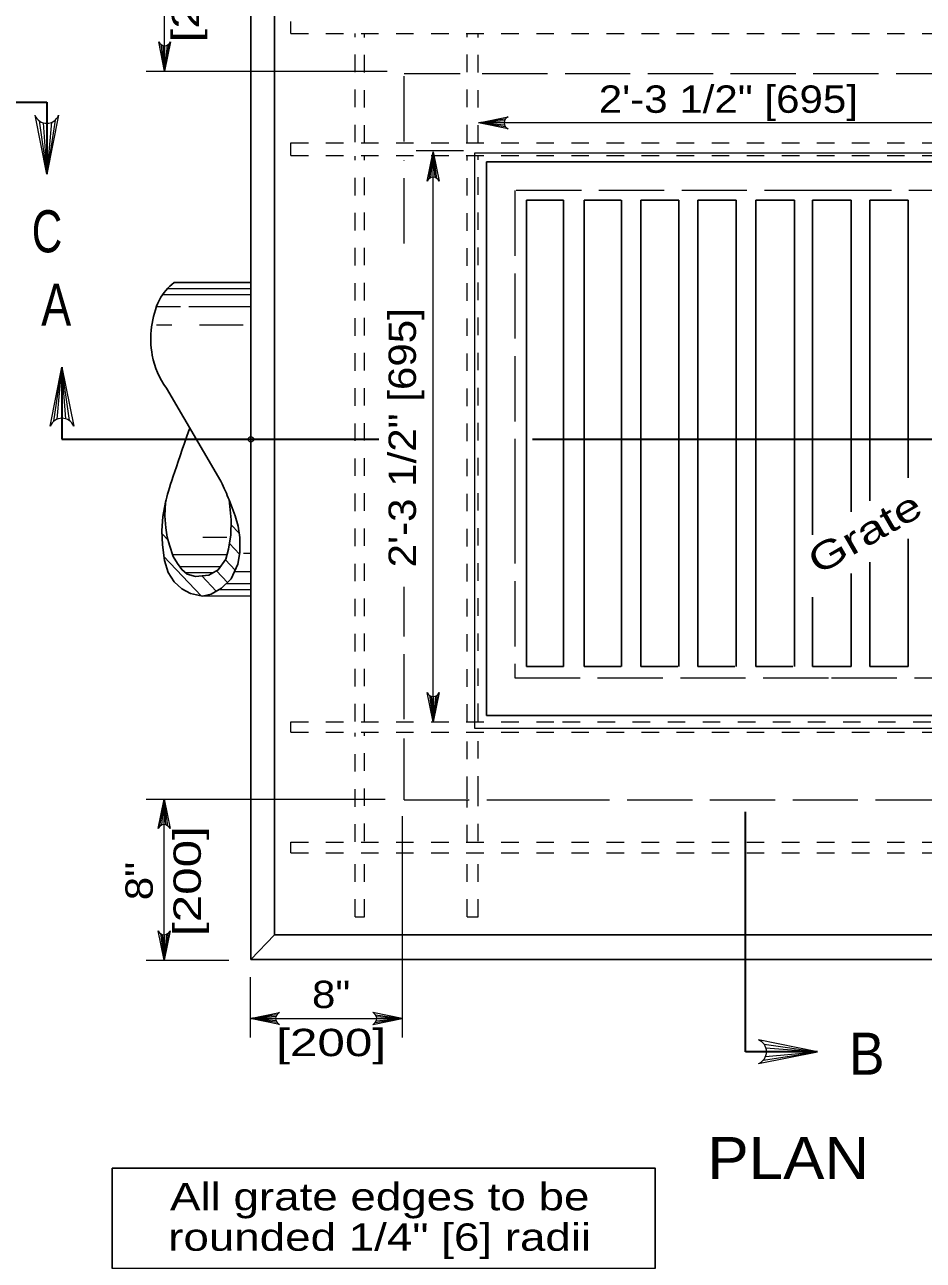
# Model space of a CAD drawing. Extents: x 1083.1 to 1117.1, y 697.4 to 719.4.
# Drawn here: x 1099.92 to 1105.05, y 708.27 to 715.32 of the extents above; entities that cross this region are included whole.
import ezdxf
from ezdxf.enums import TextEntityAlignment as Align

# ---------------------------------------------------------------- set-up
doc = ezdxf.new("R2010")
doc.units = 0
doc.header["$LTSCALE"] = 0.062
doc.header["$PDMODE"] = 32
doc.header["$PDSIZE"] = 0.031
doc.linetypes.add('DOTTED', pattern=[1.5, 0.3, -1.2])
doc.linetypes.add('LONG_DASHED', pattern=[7.5, 6, -1.5])
doc.layers.add('1', color=7, linetype='Continuous', lineweight=13)

msp = doc.modelspace()

# ---------------------------------------------------------------- linework, layer by layer
at = {"layer": '1'}
for p, q in [((1100.72158, 715.05042), (1100.72158, 715.96892)), ((1100.70025, 715.20267), (1100.72158, 715.05042)), ((1100.71083, 715.1975), (1100.72158, 715.05042)), ((1100.74517, 715.2045), (1100.72158, 715.05042)), ((1100.73525, 715.19867), (1100.72158, 715.05042)), ((1100.72158, 715.196), (1100.72158, 715.05042)), ((1100.61667, 715.05042), (1101.99075, 715.05042)), ((1100.00717, 714.76733), (1100.04975, 714.46275)), ((1100.09692, 714.77092), (1100.04975, 714.46275)), ((1102.66442, 714.77742), (1102.51208, 714.75608)), ((1102.65925, 714.76683), (1102.51208, 714.75608)), ((1100.02825, 714.757), (1100.04975, 714.46275)), ((1100.07717, 714.75925), (1100.04975, 714.46275)), ((1100.04975, 714.75392), (1100.04975, 714.46275)), ((1102.65767, 714.75608), (1102.51208, 714.75608)), ((1102.66033, 714.74242), (1102.51208, 714.75608)), ((1102.66617, 714.73258), (1102.51208, 714.75608)), ((1105.562, 714.75608), (1102.51208, 714.75608)), ((1102.426, 714.59675), (1102.15683, 714.59675)), ((1102.22967, 714.43742), (1102.25317, 714.5915)), ((1102.2395, 714.44325), (1102.25317, 714.5915)), ((1102.25317, 712.52158), (1102.25317, 714.5915)), ((1102.25317, 714.44592), (1102.25317, 714.5915)), ((1102.26392, 714.44433), (1102.25317, 714.5915)), ((1102.2745, 714.43917), (1102.25317, 714.5915)), ((1101.2135, 713.77592), (1100.709, 713.77592)), ((1101.2135, 713.81042), (1100.737, 713.81042)), ((1100.81175, 713.70667), (1100.67467, 713.70667)), ((1101.2135, 713.70667), (1100.86058, 713.70667)), ((1100.763, 713.60283), (1100.67467, 713.60283)), ((1101.16883, 713.60283), (1100.91975, 713.60283)), ((1100.08908, 713.05483), (1100.13625, 713.363)), ((1100.10883, 713.0665), (1100.13625, 713.363)), ((1100.13625, 713.07183), (1100.13625, 713.363)), ((1100.15775, 713.06867), (1100.13625, 713.363)), ((1100.17883, 713.05842), (1100.13625, 713.363)), ((1101.09133, 712.60217), (1101.08983, 712.60358)), ((1101.09675, 712.58742), (1101.09092, 712.59375)), ((1100.72275, 712.5135), (1100.714, 712.52283)), ((1100.72258, 712.51725), (1100.71458, 712.52575)), ((1100.72517, 712.56333), (1100.72192, 712.56675)), ((1102.25317, 711.34042), (1102.25317, 712.52158)), ((1101.14642, 712.41742), (1101.09983, 712.46675)), ((1100.74167, 712.37625), (1100.70733, 712.41258)), ((1101.07575, 712.39208), (1100.93883, 712.39208)), ((1101.149, 712.29717), (1101.09133, 712.35833)), ((1101.2135, 712.30067), (1101.17158, 712.30067)), ((1100.92925, 712.06025), (1100.71725, 712.2845)), ((1101.07792, 712.29392), (1100.76725, 712.29392)), ((1101.04025, 712.22483), (1100.8095, 712.22483)), ((1101.12367, 712.2065), (1101.06858, 712.26483)), ((1100.99742, 712.19025), (1100.84317, 712.19025)), ((1101.016, 712.08558), (1100.9335, 712.173)), ((1101.07992, 712.13567), (1101.01742, 712.20167)), ((1101.2135, 712.19692), (1101.11933, 712.19692)), ((1101.2135, 712.093), (1101.02925, 712.093)), ((1101.2135, 712.12758), (1101.07183, 712.12758)), ((1101.2135, 712.05842), (1100.93825, 712.05842)), ((1102.23183, 711.49267), (1102.25317, 711.34042)), ((1102.24242, 711.4875), (1102.25317, 711.34042)), ((1102.27675, 711.4945), (1102.25317, 711.34042)), ((1102.26683, 711.48867), (1102.25317, 711.34042)), ((1102.25317, 711.48592), (1102.25317, 711.34042)), ((1100.61667, 710.90025), (1101.97892, 710.90025)), ((1100.69508, 710.74617), (1100.71867, 710.90025)), ((1100.705, 710.752), (1100.71867, 710.90025)), ((1100.71867, 709.98175), (1100.71867, 710.90025)), ((1100.71867, 710.75467), (1100.71867, 710.90025)), ((1100.72942, 710.75308), (1100.71867, 710.90025)), ((1100.74, 710.74792), (1100.71867, 710.90025)), ((1102.07675, 710.80317), (1102.07675, 709.54108)), ((1100.69733, 710.134), (1100.71867, 709.98175)), ((1100.70792, 710.12892), (1100.71867, 709.98175)), ((1100.74225, 710.13583), (1100.71867, 709.98175)), ((1100.73233, 710.13), (1100.71867, 709.98175)), ((1100.71867, 710.12733), (1100.71867, 709.98175)), ((1100.61667, 709.98175), (1101.08825, 709.98175)), ((1101.20917, 709.88458), (1101.20917, 709.54108)), ((1101.3615, 709.67075), (1101.20917, 709.64942)), ((1101.35633, 709.66025), (1101.20917, 709.64942)), ((1101.20917, 709.64942), (1102.07675, 709.64942)), ((1101.35475, 709.64942), (1101.20917, 709.64942)), ((1101.35742, 709.63575), (1101.20917, 709.64942)), ((1101.36325, 709.62592), (1101.20917, 709.64942)), ((1101.92267, 709.62592), (1102.07675, 709.64942)), ((1101.92442, 709.67075), (1102.07675, 709.64942)), ((1101.9285, 709.63575), (1102.07675, 709.64942)), ((1101.92958, 709.66025), (1102.07675, 709.64942)), ((1101.93117, 709.64942), (1102.07675, 709.64942)), ((1104.14067, 709.50258), (1104.44533, 709.45992)), ((1104.151, 709.4815), (1104.44533, 709.45992)), ((1104.13708, 709.41283), (1104.44533, 709.45992)), ((1104.14875, 709.43258), (1104.44533, 709.45992)), ((1104.15417, 709.45992), (1104.44533, 709.45992))]:
    msp.add_line(p, q, dxfattribs=at)
at = {"layer": '1', "lineweight": 25}
for p, q in [((1101.2135, 709.98508), (1101.2135, 715.96917)), ((1101.34808, 710.1275), (1101.34808, 715.82667)), ((1102.55767, 714.53308), (1105.5345, 714.53308)), ((1102.55767, 711.37625), (1102.55767, 714.53308)), ((1102.78492, 711.65625), (1102.78492, 714.31583)), ((1102.78492, 714.31583), (1102.99567, 714.31583)), ((1102.99567, 711.65625), (1102.99567, 714.31583)), ((1103.11467, 714.31583), (1103.32542, 714.31583)), ((1103.32633, 711.65625), (1103.32633, 714.31583)), ((1103.43717, 711.65625), (1103.43717, 714.31583)), ((1103.43717, 714.31583), (1103.65342, 714.31583)), ((1103.7625, 714.31583), (1103.9805, 714.31583)), ((1104.09317, 714.31583), (1104.31292, 714.31583)), ((1104.09317, 713.46708), (1104.09317, 714.31583)), ((1104.31292, 713.46708), (1104.31292, 714.31583)), ((1104.4165, 714.31583), (1104.63733, 714.31583)), ((1104.4165, 713.46708), (1104.4165, 714.31583)), ((1104.63733, 712.7495), (1104.63733, 714.31583)), ((1104.74358, 714.31583), (1104.9625, 714.31583)), ((1104.74358, 712.7495), (1104.74358, 714.31583)), ((1104.9625, 712.7495), (1104.9625, 714.31583)), ((1101.2135, 713.845), (1100.776, 713.845)), ((1104.09317, 711.65625), (1104.09317, 713.46708)), ((1104.31292, 712.7495), (1104.31292, 713.46708)), ((1104.4165, 712.7495), (1104.4165, 713.46708)), ((1101.04225, 712.71275), (1100.732, 713.24342)), ((1104.31292, 712.08092), (1104.31292, 712.7495)), ((1104.4165, 712.407), (1104.4165, 712.7495)), ((1104.63733, 712.53858), (1104.63733, 712.7495)), ((1104.74358, 712.60192), (1104.74358, 712.7495)), ((1104.9625, 712.73225), (1104.9625, 712.7495)), ((1104.9625, 711.65625), (1104.9625, 712.38458)), ((1104.74358, 711.65625), (1104.74358, 712.25142)), ((1104.63733, 711.74633), (1104.63733, 712.18683)), ((1104.31292, 711.65625), (1104.31292, 712.08092)), ((1104.4165, 711.83058), (1104.4165, 712.05258)), ((1104.4165, 711.65625), (1104.4165, 711.83058)), ((1104.63733, 711.65625), (1104.63733, 711.74633)), ((1102.78492, 711.65625), (1102.99567, 711.65625)), ((1103.11467, 711.65625), (1103.32542, 711.65625)), ((1103.43717, 711.65625), (1103.64792, 711.65625)), ((1103.7625, 711.65625), (1103.97325, 711.65625)), ((1104.09317, 711.65625), (1104.30392, 711.65625)), ((1104.4165, 711.65625), (1104.63733, 711.65625)), ((1104.74358, 711.65625), (1104.9625, 711.65625)), ((1101.34808, 710.1275), (1101.2135, 709.98508)), ((1101.34808, 710.1275), (1106.73117, 710.1275)), ((1101.2135, 709.98508), (1106.86575, 709.98508))]:
    msp.add_line(p, q, dxfattribs=at)
at = {"layer": '1', "linetype": 'DOTTED'}
for p, q in [((1101.44158, 715.26525), (1101.44158, 715.33383)), ((1101.44158, 715.26525), (1106.624, 715.26525)), ((1101.80767, 714.64558), (1101.80767, 715.26483)), ((1101.86183, 714.64342), (1101.86183, 715.26033)), ((1102.4475, 714.64558), (1102.4475, 715.26142)), ((1102.50883, 714.64342), (1102.50883, 715.2625)), ((1101.44158, 714.64142), (1106.624, 714.64142)), ((1101.44158, 714.56992), (1101.44158, 714.64142)), ((1101.44158, 714.56992), (1106.624, 714.56992)), ((1101.80767, 711.34275), (1101.80767, 714.56667)), ((1101.86183, 711.34417), (1101.86183, 714.5655)), ((1102.4475, 711.34142), (1102.4475, 714.56667)), ((1102.50883, 711.34558), (1102.50883, 714.56892)), ((1101.44158, 711.28275), (1101.44158, 711.341)), ((1101.80767, 710.65733), (1101.80767, 711.27842)), ((1101.86183, 710.6615), (1101.86183, 711.28125)), ((1102.4475, 710.65317), (1102.4475, 710.89475)), ((1101.44158, 710.6545), (1106.624, 710.6545)), ((1101.44158, 710.59433), (1101.44158, 710.6545)), ((1101.44158, 710.59433), (1106.624, 710.59433)), ((1101.80767, 710.22967), (1101.80767, 710.58875)), ((1101.86183, 710.22967), (1101.86183, 710.59017)), ((1102.4475, 710.22967), (1102.4475, 710.58875)), ((1102.50883, 710.22967), (1102.50883, 710.59017)), ((1101.80767, 710.22967), (1101.86183, 710.22967)), ((1102.4475, 710.22967), (1102.50883, 710.22967))]:
    msp.add_line(p, q, dxfattribs=at)
at = {"layer": '1', "linetype": 'LONG_DASHED'}
for p, q in [((1102.08683, 714.64967), (1102.08683, 715.03767)), ((1102.08683, 715.03767), (1102.40767, 715.03767)), ((1102.53292, 715.03767), (1105.54933, 715.03767)), ((1102.08683, 714.069), (1102.08683, 714.54258)), ((1102.719, 714.37), (1102.719, 712.61533)), ((1104.5145, 714.37), (1102.719, 714.37)), ((1105.33825, 714.37), (1104.5145, 714.37)), ((1102.719, 712.61533), (1102.719, 711.591)), ((1102.08683, 711.35575), (1102.08683, 712.11008)), ((1102.08683, 710.89625), (1102.08683, 711.24683)), ((1102.08683, 710.89625), (1102.8875, 710.89625)), ((1102.8875, 710.89625), (1105.6355, 710.89625))]:
    msp.add_line(p, q, dxfattribs=at)
at = {"layer": '1', "lineweight": 35}
for p, q in [((1093.45367, 714.874), (1100.04975, 714.874)), ((1100.04975, 714.874), (1100.04975, 714.46275)), ((1100.04975, 714.72117), (1100.04975, 714.51567)), ((1100.13625, 713.363), (1100.13625, 712.95175)), ((1100.13625, 712.95175), (1101.94383, 712.95175)), ((1102.81875, 712.95175), (1107.88475, 712.95175)), ((1104.03408, 709.45992), (1104.03408, 710.8275)), ((1104.44533, 709.45992), (1104.03408, 709.45992))]:
    msp.add_line(p, q, dxfattribs=at)
at = {"layer": '1'}
for points in [[(1100.75525, 715.21858), (1100.72158, 715.05042), (1100.68792, 715.21858)], [(1100.11708, 714.79917), (1100.04975, 714.46275), (1099.9825, 714.79917)], [(1102.68033, 714.7225), (1102.51208, 714.75608), (1102.68033, 714.78975)], [(1102.21958, 714.42325), (1102.25317, 714.5915), (1102.28683, 714.42325)], [(1100.06892, 713.0265), (1100.13625, 713.363), (1100.2035, 713.0265)], [(1100.72683, 712.59308), (1100.72258, 712.51583), (1100.72892, 712.44717), (1100.73658, 712.39467), (1100.74925, 712.3475), (1100.77092, 712.28292), (1100.795, 712.24383), (1100.8205, 712.21008), (1100.85108, 712.18325), (1100.89683, 712.16975), (1100.97317, 712.1765), (1101.02792, 712.2075), (1101.07108, 712.268), (1101.08633, 712.32592), (1101.099, 712.40808), (1101.10042, 712.493), (1101.08958, 712.607)], [(1102.28683, 711.50858), (1102.25317, 711.34042), (1102.21958, 711.50858)], [(1100.685, 710.732), (1100.71867, 710.90025), (1100.75233, 710.732)], [(1100.75233, 710.15), (1100.71867, 709.98175), (1100.685, 710.15)], [(1101.37742, 709.61583), (1101.20917, 709.64942), (1101.37742, 709.68308)], [(1101.9085, 709.61583), (1102.07675, 709.64942), (1101.9085, 709.68308)], [(1104.10883, 709.39267), (1104.44533, 709.45992), (1104.10883, 709.52725)]]:
    msp.add_lwpolyline(points, dxfattribs=at)
msp.add_lwpolyline([(1102.48892, 714.58392), (1102.48892, 711.30575), (1105.60367, 711.30575), (1105.60367, 714.58392)], close=True, dxfattribs=at)
at = {"layer": '1', "lineweight": 25}
for points in [[(1103.11467, 711.65625), (1103.11467, 713.53575), (1103.11467, 714.31583)], [(1103.65342, 711.65625), (1103.65342, 713.50833), (1103.65342, 714.31583)], [(1103.7625, 711.65625), (1103.7625, 713.46708), (1103.7625, 714.31583)], [(1103.9805, 711.65625), (1103.9805, 713.46342), (1103.9805, 714.31583)], [(1101.08958, 712.607), (1101.12342, 712.5155), (1101.14017, 712.45575), (1101.15083, 712.39158), (1101.15042, 712.30592), (1101.13958, 712.24067), (1101.10025, 712.15567), (1101.04667, 712.10267), (1100.98692, 712.06942), (1100.93825, 712.05842), (1100.8685, 712.07192), (1100.8205, 712.10017), (1100.776, 712.13867), (1100.74242, 712.193), (1100.72017, 712.26133), (1100.709, 712.35008), (1100.70667, 712.4295), (1100.71192, 712.51117), (1100.72683, 712.59308)], [(1101.08958, 712.607), (1101.12342, 712.5155), (1101.14017, 712.45575), (1101.15083, 712.39158), (1101.15042, 712.30592), (1101.13958, 712.24067), (1101.10025, 712.15567), (1101.04667, 712.10267), (1100.98692, 712.06942), (1100.93825, 712.05842), (1100.8685, 712.07192), (1100.8205, 712.10017), (1100.776, 712.13867), (1100.74242, 712.193), (1100.72017, 712.26133), (1100.709, 712.35008), (1100.70667, 712.4295), (1100.71192, 712.51117), (1100.72683, 712.59308)], [(1100.72683, 712.59308), (1100.72258, 712.51583), (1100.72892, 712.44717), (1100.73658, 712.39467), (1100.74925, 712.3475), (1100.77092, 712.28292), (1100.795, 712.24383), (1100.8205, 712.21008), (1100.85108, 712.18325), (1100.89683, 712.16975), (1100.97317, 712.1765), (1101.02792, 712.2075), (1101.07108, 712.268), (1101.08633, 712.32592), (1101.099, 712.40808), (1101.10042, 712.493), (1101.08958, 712.607)], [(1102.55767, 711.37625), (1103.02333, 711.37625), (1105.21817, 711.37625)]]:
    msp.add_lwpolyline(points, dxfattribs=at)
at = {"layer": '1', "linetype": 'LONG_DASHED'}
msp.add_lwpolyline([(1102.719, 711.591), (1104.52517, 711.591), (1105.33825, 711.591)], dxfattribs=at)
at = {"layer": '1', "linetype": 'DOTTED'}
for points in [[(1101.44158, 711.341), (1102.9905, 711.341), (1105.60367, 711.341)], [(1101.44158, 711.28275), (1105.81817, 711.28275), (1106.624, 711.28275)], [(1102.4475, 710.9015), (1102.4475, 710.92875), (1102.4475, 711.27842)], [(1102.50883, 710.66008), (1102.50883, 710.93108), (1102.50883, 711.28267)]]:
    msp.add_lwpolyline(points, dxfattribs=at)
at = {"layer": '1', "lineweight": 25}
msp.add_lwpolyline([(1100.42325, 708.79667), (1103.51875, 708.79667), (1103.51875, 708.2245), (1100.42325, 708.2245)], close=True, dxfattribs=at)
at = {"layer": '1'}
for centre, radius, start, end in [((1100.72155, 715.2322), 0.03631, 202.08782, 337.91395), ((1100.04971, 714.82638), 0.07261, 202.08782, 337.91395), ((1102.6939, 714.75614), 0.03631, 112.08782, 247.91395), ((1102.25322, 714.4097), 0.03631, 22.08782, 157.91395), ((1100.13629, 712.99937), 0.07261, 22.08782, 157.91395), ((1102.25315, 711.52218), 0.03631, 202.08782, 337.91395), ((1100.71871, 710.71844), 0.03631, 22.08782, 157.91395), ((1100.71863, 710.16354), 0.03631, 202.08782, 337.91395), ((1101.39097, 709.64948), 0.03631, 112.08782, 247.91395), ((1101.89493, 709.64948), 0.03631, 292.08605, 67.91218), ((1104.08168, 709.46002), 0.07261, 292.08605, 67.91218)]:
    msp.add_arc(centre, radius, start, end, dxfattribs=at)
at = {"layer": '1', "lineweight": 25}
for centre, major_axis, start_param, end_param in [((1100.93823, 713.59838), (0, 0.30064), 0.608535, 1.0523476), ((1101.11342, 713.52633), (0, -0.49832), 4.2528342, 4.9042115), ((1101.06853, 713.51856), (0, -0.45022), 4.9073919, 5.370128)]:
    msp.add_ellipse(centre, major_axis=major_axis, ratio=0.944544, start_param=start_param, end_param=end_param, dxfattribs=at)
for points in [[(1100.72683, 712.59308), (1100.74417, 712.6645), (1100.78083, 712.779), (1100.86367, 713.01183)], [(1101.04225, 712.71275), (1101.06083, 712.67383), (1101.07642, 712.63867), (1101.08958, 712.607)]]:
    msp.add_open_spline(points, degree=3, dxfattribs=at)
at = {"layer": '1'}
msp.add_point((1101.2135, 712.95175), dxfattribs=at)

# ---------------------------------------------------------------- texts
for s, width, p in [('[200]', 1.35, (1100.91858, 715.52742)), ('[200]', 1.35, (1100.92817, 710.433)), ('8"', 1.15, (1100.65408, 710.433))]:
    msp.add_text(s, height=0.156, rotation=90, dxfattribs=dict(at, width=width)).set_placement(p, align=Align.CENTER)
for s, height, width, p in [('2\'-3 1/2" [695]', 0.156, 1.15, (1103.19758, 714.81342)), ('C', 0.24, 0.75, (1099.964, 714.01792)), ('A', 0.24, 0.8, (1100.01767, 713.59967)), ('B', 0.24, 0.95, (1104.62383, 709.32883)), ('PLAN', 0.24, 1.1, (1103.81708, 708.73392))]:
    msp.add_text(s, height=height, dxfattribs=dict(at, width=width)).set_placement(p)
for s, rotation, width, p in [('2\'-3 1/2" [695]', 90, 1.15, (1102.15483, 712.22158)), ('Grate', 30, 1.35, (1104.4485, 712.1755))]:
    msp.add_text(s, height=0.156, rotation=rotation, dxfattribs=dict(at, width=width)).set_placement(p)
for s, width, p in [('8"', 1.15, (1101.67133, 709.70892)), ('[200]', 1.35, (1101.67133, 709.43483)), ('All grate edges to be', 1.25, (1101.94817, 708.556)), ('rounded 1/4" [6] radii', 1.25, (1101.94821, 708.32525))]:
    msp.add_text(s, height=0.156, dxfattribs=dict(at, width=width)).set_placement(p, align=Align.CENTER)

doc.saveas('drawing.dxf')
